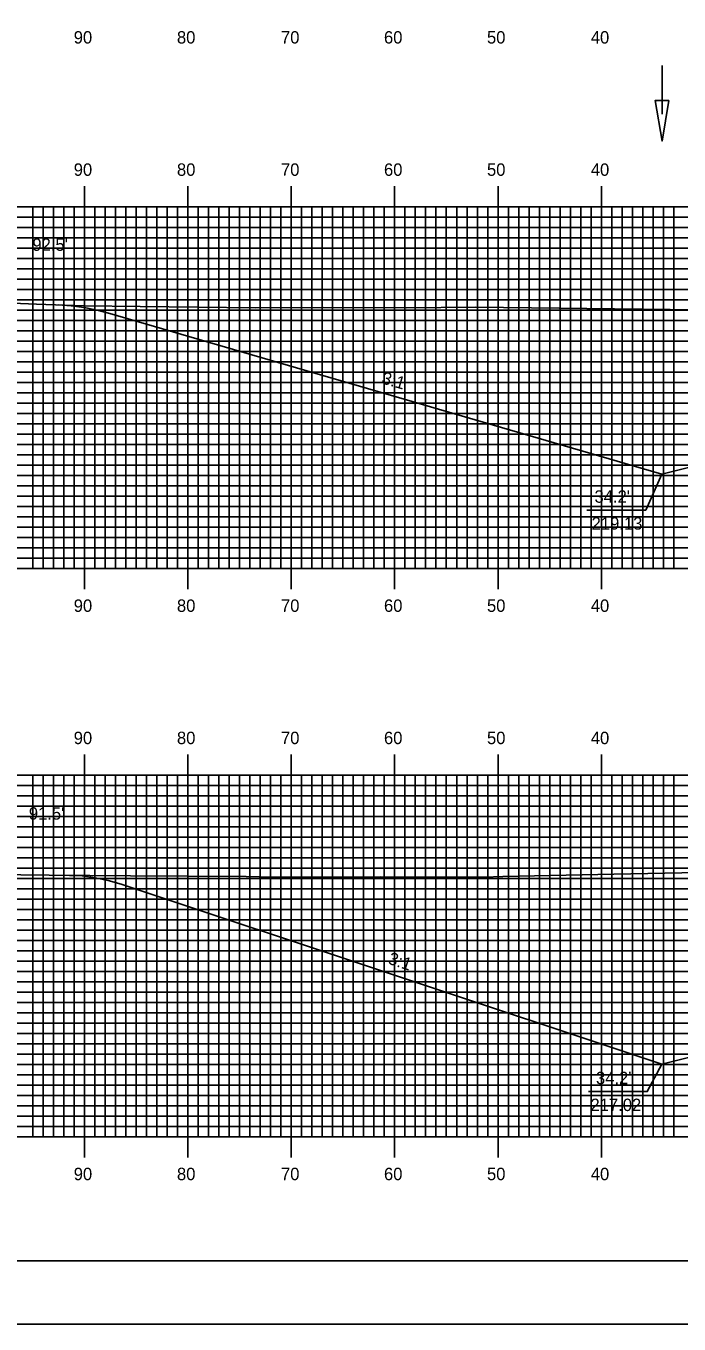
# Model space of a CAD drawing. Extents: x 1802323 to 1802666, y 442591 to 442811.
# Drawn here: x 1802393 to 1802456.1, y 442590.5 to 442716.2 of the extents above; entities that cross this region are included whole.
import ezdxf

# ---------------------------------------------------------------- set-up
doc = ezdxf.new("R2010")
doc.units = 0
for name, color, linetype in [('ANNOTATION', 7, 'Continuous'), ('BORDER', 7, 'Continuous'), ('D_Drainage_Ditch_Line', 7, 'Continuous'), ('D_Roadway_Centerline', 7, 'Continuous'), ('D_Roadway_SlopeLines', 7, 'Continuous'), ('D_Text_Standard', 7, 'Continuous'), ('H_V ANNOTATION', 7, 'Continuous'), ('MAJOR', 7, 'Continuous'), ('MINOR', 7, 'Continuous'), ('PLOT BOUNDARY', 7, 'Continuous'), ('S_Roadway_Centerline', 7, 'Continuous')]:
    doc.layers.add(name, color=color, linetype=linetype)

msp = doc.modelspace()

# ---------------------------------------------------------------- linework, layer by layer
at = {"layer": 'ANNOTATION'}
for points in [[(1802447.2, 442669.3), (1802452.89, 442669.3), (1802454.43, 442672.8)], [(1802447.34, 442613.04), (1802453.03, 442613.04), (1802454.43, 442615.69)]]:
    msp.add_lwpolyline(points, dxfattribs=at)
at = {"layer": 'BORDER'}
msp.add_lwpolyline([(1802339, 442596.67), (1802659, 442596.67), (1802659, 442806.67), (1802339, 442806.67)], close=True, dxfattribs=at)
at = {"layer": 'D_Drainage_Ditch_Line'}
msp.add_line((1802454.46, 442707.65), (1802454.46, 442712.35), dxfattribs=at)
msp.add_lwpolyline([(1802455.11, 442708.96), (1802453.8, 442708.96), (1802454.46, 442705.03)], close=True, dxfattribs=at)
at = {"layer": 'D_Roadway_Centerline'}
for points in [[(1802396.07, 442689.17), (1802397.32, 442689.09), (1802398.57, 442688.93), (1802399.82, 442688.68), (1802401.07, 442688.36), (1802454.43, 442672.8), (1802458.43, 442673.8), (1802468.6, 442676.34), (1802476.6, 442676.66), (1802488.6, 442676.9), (1802500.6, 442676.66), (1802508.6, 442676.34), (1802518.78, 442673.8), (1802522.78, 442672.8), (1802578.12, 442688.94), (1802579.37, 442689.26), (1802580.62, 442689.49), (1802581.87, 442689.62), (1802583.12, 442689.67)], [(1802397.15, 442633.97), (1802398.4, 442633.91), (1802399.65, 442633.74), (1802400.9, 442633.48), (1802402.15, 442633.11), (1802454.43, 442615.69), (1802458.43, 442616.69), (1802468.6, 442619.23), (1802476.6, 442619.55), (1802488.6, 442619.79), (1802500.6, 442619.55), (1802508.6, 442619.23), (1802518.78, 442616.69), (1802522.78, 442615.69), (1802577.02, 442633.77), (1802578.27, 442634.13), (1802579.52, 442634.39), (1802580.77, 442634.56), (1802582.02, 442634.61)]]:
    msp.add_lwpolyline(points, dxfattribs=at)
at = {"layer": 'D_Roadway_SlopeLines'}
for points in [[(1802454.43, 442672.8), (1802401.07, 442688.36), (1802399.82, 442688.68), (1802398.57, 442688.93), (1802397.32, 442689.09), (1802396.07, 442689.17)], [(1802468.6, 442676.34), (1802454.43, 442672.8)], [(1802454.43, 442615.69), (1802402.15, 442633.11), (1802400.9, 442633.48), (1802399.65, 442633.74), (1802398.4, 442633.91), (1802397.15, 442633.97)], [(1802468.6, 442619.23), (1802454.43, 442615.69)]]:
    msp.add_lwpolyline(points, dxfattribs=at)
at = {"layer": 'MAJOR'}
for p, q in [((1802398.6, 442700.67), (1802398.6, 442698.67)), ((1802408.6, 442700.67), (1802408.6, 442698.67)), ((1802418.6, 442700.67), (1802418.6, 442698.67)), ((1802428.6, 442700.67), (1802428.6, 442698.67)), ((1802438.6, 442700.67), (1802438.6, 442698.67)), ((1802448.6, 442700.67), (1802448.6, 442698.67)), ((1802348.6, 442698.67), (1802628.6, 442698.67)), ((1802348.6, 442698.67), (1802628.6, 442698.67)), ((1802398.6, 442663.67), (1802398.6, 442698.67)), ((1802408.6, 442663.67), (1802408.6, 442698.67)), ((1802418.6, 442663.67), (1802418.6, 442698.67)), ((1802428.6, 442663.67), (1802428.6, 442698.67)), ((1802438.6, 442663.67), (1802438.6, 442698.67)), ((1802448.6, 442663.67), (1802448.6, 442698.67)), ((1802348.6, 442693.67), (1802628.6, 442693.67)), ((1802348.6, 442688.67), (1802628.6, 442688.67)), ((1802348.6, 442683.67), (1802628.6, 442683.67)), ((1802348.6, 442678.67), (1802628.6, 442678.67)), ((1802348.6, 442673.67), (1802628.6, 442673.67)), ((1802348.6, 442668.67), (1802628.6, 442668.67)), ((1802348.6, 442663.67), (1802628.6, 442663.67)), ((1802348.6, 442663.67), (1802628.6, 442663.67)), ((1802398.6, 442661.66), (1802398.6, 442663.67)), ((1802408.6, 442661.66), (1802408.6, 442663.67)), ((1802418.6, 442661.66), (1802418.6, 442663.67)), ((1802428.6, 442661.66), (1802428.6, 442663.67)), ((1802438.6, 442661.66), (1802438.6, 442663.67)), ((1802448.6, 442661.66), (1802448.6, 442663.67)), ((1802398.6, 442645.67), (1802398.6, 442643.67)), ((1802408.6, 442645.67), (1802408.6, 442643.67)), ((1802418.6, 442645.67), (1802418.6, 442643.67)), ((1802428.6, 442645.67), (1802428.6, 442643.67)), ((1802438.6, 442645.67), (1802438.6, 442643.67)), ((1802448.6, 442645.67), (1802448.6, 442643.67)), ((1802348.6, 442643.67), (1802628.6, 442643.67)), ((1802348.6, 442643.67), (1802628.6, 442643.67)), ((1802398.6, 442608.67), (1802398.6, 442643.67)), ((1802408.6, 442608.67), (1802408.6, 442643.67)), ((1802418.6, 442608.67), (1802418.6, 442643.67)), ((1802428.6, 442608.67), (1802428.6, 442643.67)), ((1802438.6, 442608.67), (1802438.6, 442643.67)), ((1802448.6, 442608.67), (1802448.6, 442643.67)), ((1802348.6, 442638.67), (1802628.6, 442638.67)), ((1802348.6, 442633.67), (1802628.6, 442633.67)), ((1802348.6, 442628.67), (1802628.6, 442628.67)), ((1802348.6, 442623.67), (1802628.6, 442623.67)), ((1802348.6, 442618.67), (1802628.6, 442618.67)), ((1802348.6, 442613.67), (1802628.6, 442613.67)), ((1802348.6, 442608.67), (1802628.6, 442608.67)), ((1802348.6, 442608.67), (1802628.6, 442608.67)), ((1802398.6, 442606.66), (1802398.6, 442608.67)), ((1802408.6, 442606.66), (1802408.6, 442608.67)), ((1802418.6, 442606.66), (1802418.6, 442608.67)), ((1802428.6, 442606.66), (1802428.6, 442608.67)), ((1802438.6, 442606.66), (1802438.6, 442608.67)), ((1802448.6, 442606.66), (1802448.6, 442608.67))]:
    msp.add_line(p, q, dxfattribs=at)
at = {"layer": 'MINOR'}
for p, q in [((1802393.6, 442663.67), (1802393.6, 442698.67)), ((1802394.6, 442663.67), (1802394.6, 442698.67)), ((1802395.6, 442663.67), (1802395.6, 442698.67)), ((1802396.6, 442663.67), (1802396.6, 442698.67)), ((1802397.6, 442663.67), (1802397.6, 442698.67)), ((1802399.6, 442663.67), (1802399.6, 442698.67)), ((1802400.6, 442663.67), (1802400.6, 442698.67)), ((1802401.6, 442663.67), (1802401.6, 442698.67)), ((1802402.6, 442663.67), (1802402.6, 442698.67)), ((1802403.6, 442663.67), (1802403.6, 442698.67)), ((1802404.6, 442663.67), (1802404.6, 442698.67)), ((1802405.6, 442663.67), (1802405.6, 442698.67)), ((1802406.6, 442663.67), (1802406.6, 442698.67)), ((1802407.6, 442663.67), (1802407.6, 442698.67)), ((1802409.6, 442663.67), (1802409.6, 442698.67)), ((1802410.6, 442663.67), (1802410.6, 442698.67)), ((1802411.6, 442663.67), (1802411.6, 442698.67)), ((1802412.6, 442663.67), (1802412.6, 442698.67)), ((1802413.6, 442663.67), (1802413.6, 442698.67)), ((1802414.6, 442663.67), (1802414.6, 442698.67)), ((1802415.6, 442663.67), (1802415.6, 442698.67)), ((1802416.6, 442663.67), (1802416.6, 442698.67)), ((1802417.6, 442663.67), (1802417.6, 442698.67)), ((1802419.6, 442663.67), (1802419.6, 442698.67)), ((1802420.6, 442663.67), (1802420.6, 442698.67)), ((1802421.6, 442663.67), (1802421.6, 442698.67)), ((1802422.6, 442663.67), (1802422.6, 442698.67)), ((1802423.6, 442663.67), (1802423.6, 442698.67)), ((1802424.6, 442663.67), (1802424.6, 442698.67)), ((1802425.6, 442663.67), (1802425.6, 442698.67)), ((1802426.6, 442663.67), (1802426.6, 442698.67)), ((1802427.6, 442663.67), (1802427.6, 442698.67)), ((1802429.6, 442663.67), (1802429.6, 442698.67)), ((1802430.6, 442663.67), (1802430.6, 442698.67)), ((1802431.6, 442663.67), (1802431.6, 442698.67)), ((1802432.6, 442663.67), (1802432.6, 442698.67)), ((1802433.6, 442663.67), (1802433.6, 442698.67)), ((1802434.6, 442663.67), (1802434.6, 442698.67)), ((1802435.6, 442663.67), (1802435.6, 442698.67)), ((1802436.6, 442663.67), (1802436.6, 442698.67)), ((1802437.6, 442663.67), (1802437.6, 442698.67)), ((1802439.6, 442663.67), (1802439.6, 442698.67)), ((1802440.6, 442663.67), (1802440.6, 442698.67)), ((1802441.6, 442663.67), (1802441.6, 442698.67)), ((1802442.6, 442663.67), (1802442.6, 442698.67)), ((1802443.6, 442663.67), (1802443.6, 442698.67)), ((1802444.6, 442663.67), (1802444.6, 442698.67)), ((1802445.6, 442663.67), (1802445.6, 442698.67)), ((1802446.6, 442663.67), (1802446.6, 442698.67)), ((1802447.6, 442663.67), (1802447.6, 442698.67)), ((1802449.6, 442663.67), (1802449.6, 442698.67)), ((1802450.6, 442663.67), (1802450.6, 442698.67)), ((1802451.6, 442663.67), (1802451.6, 442698.67)), ((1802452.6, 442663.67), (1802452.6, 442698.67)), ((1802453.6, 442663.67), (1802453.6, 442698.67)), ((1802454.6, 442663.67), (1802454.6, 442698.67)), ((1802455.6, 442663.67), (1802455.6, 442698.67)), ((1802348.6, 442697.67), (1802628.6, 442697.67)), ((1802348.6, 442696.67), (1802628.6, 442696.67)), ((1802348.6, 442695.67), (1802628.6, 442695.67)), ((1802348.6, 442694.67), (1802628.6, 442694.67)), ((1802348.6, 442692.67), (1802628.6, 442692.67)), ((1802348.6, 442691.67), (1802628.6, 442691.67)), ((1802348.6, 442690.67), (1802628.6, 442690.67)), ((1802348.6, 442689.67), (1802628.6, 442689.67)), ((1802348.6, 442687.67), (1802628.6, 442687.67)), ((1802348.6, 442686.67), (1802628.6, 442686.67)), ((1802348.6, 442685.67), (1802628.6, 442685.67)), ((1802348.6, 442684.67), (1802628.6, 442684.67)), ((1802348.6, 442682.67), (1802628.6, 442682.67)), ((1802348.6, 442681.67), (1802628.6, 442681.67)), ((1802348.6, 442680.67), (1802628.6, 442680.67)), ((1802348.6, 442679.67), (1802628.6, 442679.67)), ((1802348.6, 442677.67), (1802628.6, 442677.67)), ((1802348.6, 442676.67), (1802628.6, 442676.67)), ((1802348.6, 442675.67), (1802628.6, 442675.67)), ((1802348.6, 442674.67), (1802628.6, 442674.67)), ((1802348.6, 442672.67), (1802628.6, 442672.67)), ((1802348.6, 442671.67), (1802628.6, 442671.67)), ((1802348.6, 442670.67), (1802628.6, 442670.67)), ((1802348.6, 442669.67), (1802628.6, 442669.67)), ((1802348.6, 442667.67), (1802628.6, 442667.67)), ((1802348.6, 442666.67), (1802628.6, 442666.67)), ((1802348.6, 442665.67), (1802628.6, 442665.67)), ((1802348.6, 442664.67), (1802628.6, 442664.67)), ((1802393.6, 442608.67), (1802393.6, 442643.67)), ((1802394.6, 442608.67), (1802394.6, 442643.67)), ((1802395.6, 442608.67), (1802395.6, 442643.67)), ((1802396.6, 442608.67), (1802396.6, 442643.67)), ((1802397.6, 442608.67), (1802397.6, 442643.67)), ((1802399.6, 442608.67), (1802399.6, 442643.67)), ((1802400.6, 442608.67), (1802400.6, 442643.67)), ((1802401.6, 442608.67), (1802401.6, 442643.67)), ((1802402.6, 442608.67), (1802402.6, 442643.67)), ((1802403.6, 442608.67), (1802403.6, 442643.67)), ((1802404.6, 442608.67), (1802404.6, 442643.67)), ((1802405.6, 442608.67), (1802405.6, 442643.67)), ((1802406.6, 442608.67), (1802406.6, 442643.67)), ((1802407.6, 442608.67), (1802407.6, 442643.67)), ((1802409.6, 442608.67), (1802409.6, 442643.67)), ((1802410.6, 442608.67), (1802410.6, 442643.67)), ((1802411.6, 442608.67), (1802411.6, 442643.67)), ((1802412.6, 442608.67), (1802412.6, 442643.67)), ((1802413.6, 442608.67), (1802413.6, 442643.67)), ((1802414.6, 442608.67), (1802414.6, 442643.67)), ((1802415.6, 442608.67), (1802415.6, 442643.67)), ((1802416.6, 442608.67), (1802416.6, 442643.67)), ((1802417.6, 442608.67), (1802417.6, 442643.67)), ((1802419.6, 442608.67), (1802419.6, 442643.67)), ((1802420.6, 442608.67), (1802420.6, 442643.67)), ((1802421.6, 442608.67), (1802421.6, 442643.67)), ((1802422.6, 442608.67), (1802422.6, 442643.67)), ((1802423.6, 442608.67), (1802423.6, 442643.67)), ((1802424.6, 442608.67), (1802424.6, 442643.67)), ((1802425.6, 442608.67), (1802425.6, 442643.67)), ((1802426.6, 442608.67), (1802426.6, 442643.67)), ((1802427.6, 442608.67), (1802427.6, 442643.67)), ((1802429.6, 442608.67), (1802429.6, 442643.67)), ((1802430.6, 442608.67), (1802430.6, 442643.67)), ((1802431.6, 442608.67), (1802431.6, 442643.67)), ((1802432.6, 442608.67), (1802432.6, 442643.67)), ((1802433.6, 442608.67), (1802433.6, 442643.67)), ((1802434.6, 442608.67), (1802434.6, 442643.67)), ((1802435.6, 442608.67), (1802435.6, 442643.67)), ((1802436.6, 442608.67), (1802436.6, 442643.67)), ((1802437.6, 442608.67), (1802437.6, 442643.67)), ((1802439.6, 442608.67), (1802439.6, 442643.67)), ((1802440.6, 442608.67), (1802440.6, 442643.67)), ((1802441.6, 442608.67), (1802441.6, 442643.67)), ((1802442.6, 442608.67), (1802442.6, 442643.67)), ((1802443.6, 442608.67), (1802443.6, 442643.67)), ((1802444.6, 442608.67), (1802444.6, 442643.67)), ((1802445.6, 442608.67), (1802445.6, 442643.67)), ((1802446.6, 442608.67), (1802446.6, 442643.67)), ((1802447.6, 442608.67), (1802447.6, 442643.67)), ((1802449.6, 442608.67), (1802449.6, 442643.67)), ((1802450.6, 442608.67), (1802450.6, 442643.67)), ((1802451.6, 442608.67), (1802451.6, 442643.67)), ((1802452.6, 442608.67), (1802452.6, 442643.67)), ((1802453.6, 442608.67), (1802453.6, 442643.67)), ((1802454.6, 442608.67), (1802454.6, 442643.67)), ((1802455.6, 442608.67), (1802455.6, 442643.67)), ((1802348.6, 442642.67), (1802628.6, 442642.67)), ((1802348.6, 442641.67), (1802628.6, 442641.67)), ((1802348.6, 442640.67), (1802628.6, 442640.67)), ((1802348.6, 442639.67), (1802628.6, 442639.67)), ((1802348.6, 442637.67), (1802628.6, 442637.67)), ((1802348.6, 442636.67), (1802628.6, 442636.67)), ((1802348.6, 442635.67), (1802628.6, 442635.67)), ((1802348.6, 442634.67), (1802628.6, 442634.67)), ((1802348.6, 442632.67), (1802628.6, 442632.67)), ((1802348.6, 442631.67), (1802628.6, 442631.67)), ((1802348.6, 442630.67), (1802628.6, 442630.67)), ((1802348.6, 442629.67), (1802628.6, 442629.67)), ((1802348.6, 442627.67), (1802628.6, 442627.67)), ((1802348.6, 442626.67), (1802628.6, 442626.67)), ((1802348.6, 442625.67), (1802628.6, 442625.67)), ((1802348.6, 442624.67), (1802628.6, 442624.67)), ((1802348.6, 442622.67), (1802628.6, 442622.67)), ((1802348.6, 442621.67), (1802628.6, 442621.67)), ((1802348.6, 442620.67), (1802628.6, 442620.67)), ((1802348.6, 442619.67), (1802628.6, 442619.67)), ((1802348.6, 442617.67), (1802628.6, 442617.67)), ((1802348.6, 442616.67), (1802628.6, 442616.67)), ((1802348.6, 442615.67), (1802628.6, 442615.67)), ((1802348.6, 442614.67), (1802628.6, 442614.67)), ((1802348.6, 442612.67), (1802628.6, 442612.67)), ((1802348.6, 442611.67), (1802628.6, 442611.67)), ((1802348.6, 442610.67), (1802628.6, 442610.67)), ((1802348.6, 442609.67), (1802628.6, 442609.67))]:
    msp.add_line(p, q, dxfattribs=at)
at = {"layer": 'PLOT BOUNDARY'}
msp.add_lwpolyline([(1802322.81, 442590.55), (1802662.81, 442590.55), (1802662.81, 442810.55), (1802322.81, 442810.55)], close=True, dxfattribs=at)
at = {"layer": 'S_Roadway_Centerline'}
for points in [[(1802386.15, 442689.57), (1802393.97, 442689.24), (1802398.55, 442689.09), (1802403.98, 442689.02), (1802415.14, 442688.89), (1802421.74, 442688.91), (1802429.72, 442688.89), (1802436.44, 442688.95), (1802455.25, 442688.74), (1802457.75, 442688.7), (1802475.15, 442689.57), (1802479.26, 442689.76), (1802479.55, 442689.78), (1802479.89, 442689.76), (1802491.93, 442689.49), (1802500.39, 442689.33), (1802503.32, 442689.37), (1802507.23, 442689.68), (1802521.77, 442689.85)], [(1802386.95, 442634.08), (1802395.18, 442633.99), (1802403.07, 442633.91), (1802414.26, 442633.85), (1802415.51, 442633.82), (1802416.43, 442633.81), (1802427.25, 442633.83), (1802437.24, 442633.81), (1802439.05, 442633.85), (1802449.8, 442634.07), (1802459.65, 442634.28), (1802461.93, 442634.36), (1802464.62, 442634.32), (1802473.33, 442634.27), (1802479.98, 442634.01), (1802490.3, 442634), (1802501.57, 442634.31), (1802507.7, 442634.41), (1802516.07, 442634.75), (1802519.95, 442634.88)]]:
    msp.add_lwpolyline(points, dxfattribs=at)

# ---------------------------------------------------------------- texts
at = {"layer": 'ANNOTATION'}
for rotation, p in [(343.7398, (1802427.27, 442681.6)), (341.5651, (1802427.89, 442625.44))]:
    msp.add_text('3:1', height=1.2, rotation=rotation, dxfattribs=at).set_placement(p)
for s, p in [("34.2'", (1802447.93, 442670.03)), ('219.13', (1802447.65, 442667.43)), ("34.2'", (1802448.07, 442613.76)), ('217.02', (1802447.54, 442611.16))]:
    msp.add_text(s, height=1.2, dxfattribs=at).set_placement(p)
at = {"layer": 'D_Text_Standard'}
for s, p in [("92.5'", (1802393.57, 442694.41)), ("91.5'", (1802393.23, 442639.36))]:
    msp.add_text(s, height=1.2, dxfattribs=at).set_placement(p)
at = {"layer": 'H_V ANNOTATION'}
for s, p in [('90', (1802397.57, 442714.47)), ('80', (1802407.55, 442714.47)), ('70', (1802417.61, 442714.47)), ('60', (1802427.57, 442714.47)), ('50', (1802437.53, 442714.47)), ('40', (1802447.57, 442714.47)), ('90', (1802397.57, 442701.67)), ('80', (1802407.55, 442701.67)), ('70', (1802417.61, 442701.67)), ('60', (1802427.57, 442701.67)), ('50', (1802437.53, 442701.67)), ('40', (1802447.57, 442701.67)), ('90', (1802397.57, 442659.47)), ('80', (1802407.55, 442659.47)), ('70', (1802417.61, 442659.47)), ('60', (1802427.57, 442659.47)), ('50', (1802437.53, 442659.47)), ('40', (1802447.57, 442659.47)), ('90', (1802397.57, 442646.67)), ('80', (1802407.55, 442646.67)), ('70', (1802417.61, 442646.67)), ('60', (1802427.57, 442646.67)), ('50', (1802437.53, 442646.67)), ('40', (1802447.57, 442646.67)), ('90', (1802397.57, 442604.47)), ('80', (1802407.55, 442604.47)), ('70', (1802417.61, 442604.47)), ('60', (1802427.57, 442604.47)), ('50', (1802437.53, 442604.47)), ('40', (1802447.57, 442604.47))]:
    msp.add_text(s, height=1.2, dxfattribs=at).set_placement(p)

doc.saveas('drawing.dxf')
